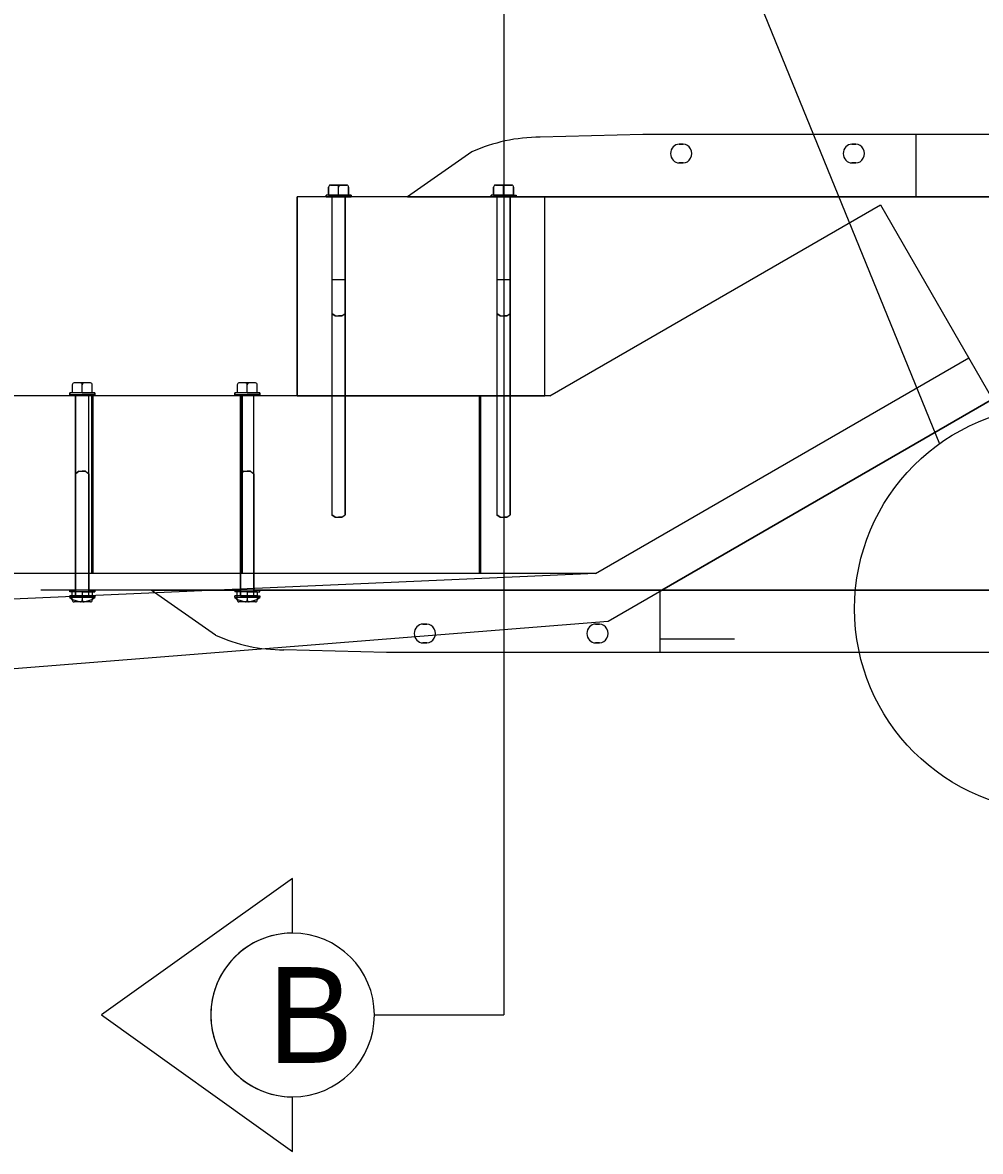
# Model space of a CAD drawing. Extents: x 10028 to 81668, y 3581 to 11018.
# Drawn here: x 17603.6 to 17755.7, y 8654.7 to 8833.9 of the extents above; entities that cross this region are included whole.
import ezdxf

# ---------------------------------------------------------------- set-up
doc = ezdxf.new("R2010")
doc.units = 0
for name, color, linetype in [('conPaving', 7, 'Continuous'), ('dsnCellsNorthArrow', 7, 'Continuous'), ('dsnTextTabulation', 7, 'Continuous'), ('Level 9', 7, 'Continuous')]:
    doc.layers.add(name, color=color, linetype=linetype)

msp = doc.modelspace()

# ---------------------------------------------------------------- linework, layer by layer
at = {"layer": 'conPaving'}
for p, q in [((17702.09, 8816.12), (17685.78, 8815.68)), ((17987.17, 8816.12), (17702.09, 8816.12)), ((17674.94, 8813.36), (17664.69, 8806.21)), ((17707.85, 8814.58), (17708.52, 8814.58)), ((17735.28, 8814.58), (17735.95, 8814.58)), ((17708.52, 8811.61), (17707.85, 8811.61)), ((17735.95, 8811.61), (17735.28, 8811.61)), ((17652.17, 8807.76), (17652.17, 8806.5)), ((17654.04, 8808.08), (17652.45, 8808.08)), ((17655.07, 8808.08), (17654.04, 8808.08)), ((17655.35, 8806.5), (17655.35, 8807.76)), ((17652.17, 8806.5), (17651.77, 8806.5)), ((17651.77, 8806.5), (17651.77, 8806.21)), ((17651.77, 8806.21), (17652.7, 8806.21)), ((17652.7, 8806.21), (17652.7, 8787.72)), ((17654.82, 8787.72), (17654.82, 8806.21)), ((17654.82, 8806.21), (17655.75, 8806.21)), ((17655.75, 8806.5), (17655.35, 8806.5)), ((17655.75, 8806.21), (17655.75, 8806.5)), ((17664.69, 8806.21), (17678.91, 8806.21)), ((17678.91, 8806.21), (17678.91, 8787.72)), ((17681.03, 8787.72), (17681.03, 8806.21)), ((17681.03, 8806.21), (18008.23, 8806.21)), ((17652.7, 8793.03), (17652.7, 8755.74)), ((17654.82, 8793.03), (17652.7, 8793.03)), ((17654.82, 8755.74), (17654.82, 8793.03)), ((17678.91, 8793.03), (17678.91, 8755.74)), ((17681.03, 8793.03), (17678.91, 8793.03)), ((17681.03, 8755.74), (17681.03, 8793.03)), ((17652.7, 8787.72), (17653.23, 8787.34)), ((17653.23, 8787.34), (17653.76, 8787.34)), ((17653.76, 8787.34), (17654.29, 8787.34)), ((17654.29, 8787.34), (17654.82, 8787.72)), ((17678.91, 8787.72), (17679.44, 8787.34)), ((17679.44, 8787.34), (17679.97, 8787.34)), ((17679.97, 8787.34), (17680.5, 8787.34)), ((17680.5, 8787.34), (17681.03, 8787.72)), ((17611.45, 8776.37), (17611.45, 8775.11)), ((17613.32, 8776.68), (17611.73, 8776.68)), ((17614.35, 8776.68), (17613.32, 8776.68)), ((17614.63, 8775.11), (17614.63, 8776.37)), ((17637.66, 8776.37), (17637.66, 8775.11)), ((17639.54, 8776.68), (17637.94, 8776.68)), ((17640.56, 8776.68), (17639.54, 8776.68)), ((17640.85, 8775.11), (17640.85, 8776.37)), ((17611.45, 8775.11), (17611.05, 8775.11)), ((17611.05, 8775.11), (17611.05, 8774.81)), ((17611.05, 8774.81), (17611.98, 8774.81)), ((17611.98, 8774.81), (17611.98, 8742.89)), ((17614.1, 8742.89), (17614.1, 8774.81)), ((17614.1, 8774.81), (17615.03, 8774.81)), ((17615.03, 8775.11), (17614.63, 8775.11)), ((17615.03, 8774.81), (17615.03, 8775.11)), ((17637.66, 8775.11), (17637.26, 8775.11)), ((17637.26, 8775.11), (17637.26, 8774.81)), ((17637.26, 8774.81), (17638.19, 8774.81)), ((17638.19, 8774.81), (17638.19, 8742.89)), ((17640.31, 8742.89), (17640.31, 8774.81)), ((17640.31, 8774.81), (17641.24, 8774.81)), ((17641.24, 8775.11), (17640.85, 8775.11)), ((17641.24, 8774.81), (17641.24, 8775.11)), ((17611.98, 8762.26), (17612.51, 8762.65)), ((17611.98, 8743.77), (17611.98, 8762.26)), ((17612.51, 8762.65), (17613.04, 8762.65)), ((17613.04, 8762.65), (17613.57, 8762.65)), ((17613.57, 8762.65), (17614.1, 8762.26)), ((17614.1, 8762.26), (17614.1, 8743.77)), ((17638.19, 8762.26), (17638.72, 8762.65)), ((17638.19, 8743.77), (17638.19, 8762.26)), ((17638.72, 8762.65), (17639.25, 8762.65)), ((17639.25, 8762.65), (17639.78, 8762.65)), ((17639.78, 8762.65), (17640.31, 8762.26)), ((17640.31, 8762.26), (17640.31, 8743.77)), ((17652.7, 8755.74), (17653.23, 8755.35)), ((17654.29, 8755.35), (17654.82, 8755.74)), ((17678.91, 8755.74), (17679.44, 8755.35)), ((17680.5, 8755.35), (17681.03, 8755.74)), ((17653.23, 8755.35), (17653.76, 8755.35)), ((17653.76, 8755.35), (17654.29, 8755.35)), ((17679.44, 8755.35), (17679.97, 8755.35)), ((17679.97, 8755.35), (17680.5, 8755.35)), ((17611.05, 8743.48), (17611.05, 8743.77)), ((17611.05, 8743.77), (17611.98, 8743.77)), ((17611.45, 8743.48), (17611.05, 8743.48)), ((17611.45, 8742.22), (17611.45, 8743.48)), ((17614.1, 8743.77), (17615.03, 8743.77)), ((17615.03, 8743.48), (17614.63, 8743.48)), ((17614.63, 8743.48), (17614.63, 8742.22)), ((17615.03, 8743.77), (17615.03, 8743.48)), ((17634.22, 8736.63), (17623.97, 8743.77)), ((17623.97, 8743.77), (17638.19, 8743.77)), ((17640.31, 8743.77), (17967.51, 8743.77)), ((17613.32, 8741.91), (17611.73, 8741.91)), ((17611.98, 8742.89), (17614.1, 8742.89)), ((17614.35, 8741.91), (17613.32, 8741.91)), ((17638.19, 8742.89), (17640.31, 8742.89)), ((17667.8, 8738.38), (17667.13, 8738.38)), ((17695.23, 8738.38), (17694.56, 8738.38)), ((17661.37, 8733.87), (17645.06, 8734.3)), ((17667.13, 8735.41), (17667.8, 8735.41)), ((17694.56, 8735.41), (17695.23, 8735.41)), ((17946.45, 8733.87), (17661.37, 8733.87))]:
    msp.add_line(p, q, dxfattribs=at)
msp.add_lwpolyline([(17757.63, 8774.09), (17705.12, 8743.77), (17769.47, 8743.77), (17769.47, 8752.59)], dxfattribs=at)
for centre in [(17613.04, 8745.29), (17639.25, 8745.29)]:
    msp.add_arc(centre, 3.35, 233.5244, 306.4756, dxfattribs=at)
for centre, major_axis, ratio, start_param, end_param in [((17685.78, 8790.15), (-25.97, 0), 0.98332, 4.712389, 5.142831), ((17707.85, 8813.09), (0, -1.49), 0.899999, 3.141593, 6.283185), ((17708.52, 8813.09), (0, -1.49), 0.899999, 0, 3.141593), ((17735.28, 8813.09), (0, -1.49), 0.899999, 3.141593, 6.283185), ((17735.95, 8813.09), (0, -1.49), 0.899999, 0, 3.141593), ((17652.45, 8807.76), (0, -0.315), 0.899999, 3.141593, 4.712389), ((17655.07, 8807.76), (0, -0.315), 0.899999, 1.570796, 3.141593), ((17611.73, 8776.37), (0, -0.315), 0.899999, 3.141593, 4.712389), ((17614.35, 8776.37), (0, -0.315), 0.899999, 1.570796, 3.141593), ((17637.94, 8776.37), (0, -0.315), 0.899999, 3.141593, 4.712389), ((17640.56, 8776.37), (0, -0.315), 0.899999, 1.570796, 3.141593), ((17611.73, 8742.22), (0, -0.315), 0.899999, 4.712389, 6.283185), ((17614.35, 8742.22), (0, -0.315), 0.899999, 6.283185, 7.853982), ((17667.13, 8736.89), (0, -1.49), 0.899999, 3.141593, 6.283185), ((17667.8, 8736.89), (0, -1.49), 0.899999, 0, 3.141593), ((17694.56, 8736.89), (0, -1.49), 0.899999, 3.141593, 6.283185), ((17695.23, 8736.89), (0, -1.49), 0.899999, 0, 3.141593), ((17645.06, 8759.83), (-25.97, 0), 0.98332, 1.140354, 1.570796)]:
    msp.add_ellipse(centre, major_axis=major_axis, ratio=ratio, start_param=start_param, end_param=end_param, dxfattribs=at)
at = {"layer": 'dsnCellsNorthArrow'}
for p, q in [((17646.45, 8697.99), (17616.11, 8676.33)), ((17646.45, 8689.33), (17646.45, 8697.99)), ((17616.11, 8676.33), (17646.45, 8654.66)), ((17646.45, 8654.66), (17646.45, 8663.32))]:
    msp.add_line(p, q, dxfattribs=at)
for start, end in [(89.9948, 270.0052), (90.0052, 269.9948), (270.0052, 89.9948)]:
    msp.add_arc((17646.45, 8676.32), 13, start, end, dxfattribs=at)
at = {"layer": 'dsnTextTabulation'}
for p, q in [((17681.71, 8932.58), (17749.2, 8767.02)), ((17680.01, 8865.47), (17680.01, 8676.32)), ((17687.31, 8774.63), (17739.82, 8804.94)), ((17739.82, 8804.94), (17757.63, 8774.09)), ((17694.57, 8746.43), (17753.85, 8780.65)), ((17687.31, 8774.63), (17511.6, 8774.63)), ((17614.49, 8774.63), (17614.49, 8746.43)), ((17614.71, 8774.63), (17614.71, 8746.43)), ((17638.24, 8774.63), (17638.24, 8746.43)), ((17638.46, 8774.63), (17638.46, 8746.43)), ((17676.09, 8774.63), (17676.09, 8746.43)), ((17676.31, 8774.63), (17676.31, 8746.43)), ((17696.58, 8738.84), (17757.63, 8774.09)), ((17694.57, 8746.43), (17511.6, 8746.43)), ((17511.8, 8724.18), (17696.58, 8738.84)), ((17659.45, 8676.32), (17680.01, 8676.32))]:
    msp.add_line(p, q, dxfattribs=at)
at = {"layer": 'Level 9'}
for p, q in [((17987.17, 8816.12), (17702.09, 8816.12)), ((17745.51, 8806.21), (17745.51, 8816.12)), ((17652.17, 8807.76), (17652.17, 8806.5)), ((17652.17, 8806.5), (17652.17, 8807.76)), ((17652.17, 8806.5), (17652.17, 8807.76)), ((17654.04, 8808.08), (17652.45, 8808.08)), ((17652.45, 8808.08), (17653.47, 8808.08)), ((17652.45, 8808.08), (17653.47, 8808.08)), ((17653.47, 8808.08), (17655.07, 8808.08)), ((17653.47, 8808.08), (17655.07, 8808.08)), ((17653.76, 8806.5), (17653.76, 8807.76)), ((17653.76, 8806.5), (17653.76, 8807.76)), ((17653.76, 8806.5), (17653.76, 8807.76)), ((17655.07, 8808.08), (17654.04, 8808.08)), ((17655.35, 8806.5), (17655.35, 8807.76)), ((17655.35, 8807.76), (17655.35, 8806.5)), ((17655.35, 8807.76), (17655.35, 8806.5)), ((17678.38, 8807.76), (17678.38, 8806.5)), ((17678.38, 8806.5), (17678.38, 8807.76)), ((17678.38, 8806.5), (17678.38, 8807.76)), ((17680.26, 8808.08), (17678.66, 8808.08)), ((17678.66, 8808.08), (17679.69, 8808.08)), ((17678.66, 8808.08), (17679.69, 8808.08)), ((17679.69, 8808.08), (17681.28, 8808.08)), ((17679.69, 8808.08), (17681.28, 8808.08)), ((17679.97, 8806.5), (17679.97, 8807.76)), ((17679.97, 8806.5), (17679.97, 8807.76)), ((17679.97, 8806.5), (17679.97, 8807.76)), ((17681.28, 8808.08), (17680.26, 8808.08)), ((17681.57, 8806.5), (17681.57, 8807.76)), ((17681.57, 8807.76), (17681.57, 8806.5)), ((17681.57, 8807.76), (17681.57, 8806.5)), ((18042.06, 8806.21), (17647.2, 8806.21)), ((17647.2, 8806.21), (17647.2, 8774.63)), ((17686.53, 8806.21), (17647.2, 8806.21)), ((17647.2, 8774.63), (17647.2, 8806.21)), ((17653.76, 8806.5), (17651.77, 8806.5)), ((17651.77, 8806.21), (17651.77, 8806.5)), ((17653.76, 8806.5), (17651.77, 8806.5)), ((17651.77, 8806.5), (17651.77, 8806.21)), ((17653.76, 8806.5), (17651.77, 8806.5)), ((17651.77, 8806.5), (17651.77, 8806.21)), ((17655.75, 8806.21), (17651.77, 8806.21)), ((17651.77, 8806.21), (17655.75, 8806.21)), ((17651.77, 8806.21), (17655.75, 8806.21)), ((17655.35, 8806.5), (17652.17, 8806.5)), ((17652.17, 8806.5), (17655.35, 8806.5)), ((17652.17, 8806.5), (17655.35, 8806.5)), ((17653.76, 8806.21), (17652.7, 8806.21)), ((17652.7, 8806.21), (17652.7, 8787.72)), ((17653.76, 8806.5), (17655.75, 8806.5)), ((17653.76, 8806.5), (17655.75, 8806.5)), ((17653.76, 8806.5), (17655.75, 8806.5)), ((17653.76, 8806.21), (17654.82, 8806.21)), ((17653.76, 8806.21), (17654.82, 8806.21)), ((17654.82, 8806.21), (17654.82, 8787.72)), ((17655.75, 8806.5), (17655.75, 8806.21)), ((17655.75, 8806.21), (17655.75, 8806.5)), ((17655.75, 8806.21), (17655.75, 8806.5)), ((17679.97, 8806.5), (17677.98, 8806.5)), ((17677.98, 8806.21), (17677.98, 8806.5)), ((17679.97, 8806.5), (17677.98, 8806.5)), ((17677.98, 8806.5), (17677.98, 8806.21)), ((17679.97, 8806.5), (17677.98, 8806.5)), ((17677.98, 8806.5), (17677.98, 8806.21)), ((17681.96, 8806.21), (17677.98, 8806.21)), ((17677.98, 8806.21), (17681.96, 8806.21)), ((17677.98, 8806.21), (17681.96, 8806.21)), ((17681.57, 8806.5), (17678.38, 8806.5)), ((17678.38, 8806.5), (17681.57, 8806.5)), ((17678.38, 8806.5), (17681.57, 8806.5)), ((17679.97, 8806.21), (17678.91, 8806.21)), ((17678.91, 8806.21), (17678.91, 8787.72)), ((17679.97, 8806.5), (17681.96, 8806.5)), ((17679.97, 8806.5), (17681.96, 8806.5)), ((17679.97, 8806.5), (17681.96, 8806.5)), ((17679.97, 8806.21), (17681.03, 8806.21)), ((17679.97, 8806.21), (17681.03, 8806.21)), ((17681.03, 8806.21), (17681.03, 8787.72)), ((17681.96, 8806.5), (17681.96, 8806.21)), ((17681.96, 8806.21), (17681.96, 8806.5)), ((17681.96, 8806.21), (17681.96, 8806.5)), ((17686.53, 8774.63), (17686.53, 8806.21)), ((17686.53, 8774.63), (17686.53, 8806.21)), ((17652.7, 8793.03), (17652.7, 8755.74)), ((17654.82, 8793.03), (17654.82, 8755.74)), ((17678.91, 8793.03), (17678.91, 8755.74)), ((17681.03, 8793.03), (17681.03, 8755.74)), ((17653.23, 8787.34), (17652.7, 8787.72)), ((17653.23, 8787.34), (17653.76, 8787.34)), ((17654.29, 8787.34), (17653.76, 8787.34)), ((17654.29, 8787.34), (17654.82, 8787.72)), ((17679.44, 8787.34), (17678.91, 8787.72)), ((17679.44, 8787.34), (17679.97, 8787.34)), ((17680.5, 8787.34), (17679.97, 8787.34)), ((17680.5, 8787.34), (17681.03, 8787.72)), ((17611.45, 8776.37), (17611.45, 8775.11)), ((17613.32, 8776.68), (17611.73, 8776.68)), ((17613.04, 8775.11), (17613.04, 8776.37)), ((17614.35, 8776.68), (17613.32, 8776.68)), ((17614.63, 8775.11), (17614.63, 8776.37)), ((17637.66, 8776.37), (17637.66, 8775.11)), ((17639.54, 8776.68), (17637.94, 8776.68)), ((17639.25, 8775.11), (17639.25, 8776.37)), ((17640.56, 8776.68), (17639.54, 8776.68)), ((17640.85, 8775.11), (17640.85, 8776.37)), ((17613.04, 8775.11), (17611.05, 8775.11)), ((17611.05, 8774.81), (17611.05, 8775.11)), ((17615.03, 8774.81), (17611.05, 8774.81)), ((17614.63, 8775.11), (17611.45, 8775.11)), ((17613.04, 8774.81), (17611.98, 8774.81)), ((17611.98, 8742.89), (17611.98, 8774.81)), ((17613.04, 8775.11), (17615.03, 8775.11)), ((17614.1, 8742.89), (17614.1, 8774.81)), ((17615.03, 8775.11), (17615.03, 8774.81)), ((17639.25, 8775.11), (17637.26, 8775.11)), ((17637.26, 8774.81), (17637.26, 8775.11)), ((17641.24, 8774.81), (17637.26, 8774.81)), ((17640.85, 8775.11), (17637.66, 8775.11)), ((17639.25, 8774.81), (17638.19, 8774.81)), ((17638.19, 8742.89), (17638.19, 8774.81)), ((17639.25, 8775.11), (17641.24, 8775.11)), ((17640.31, 8742.89), (17640.31, 8774.81)), ((17641.24, 8775.11), (17641.24, 8774.81)), ((17647.2, 8774.63), (17686.53, 8774.63)), ((17647.2, 8774.63), (17686.53, 8774.63)), ((17647.2, 8774.63), (17686.53, 8774.63)), ((17612.51, 8762.65), (17611.98, 8762.26)), ((17611.98, 8743.77), (17611.98, 8762.26)), ((17612.51, 8762.65), (17613.04, 8762.65)), ((17613.57, 8762.65), (17613.04, 8762.65)), ((17613.57, 8762.65), (17614.1, 8762.26)), ((17614.1, 8743.77), (17614.1, 8762.26)), ((17638.72, 8762.65), (17638.19, 8762.26)), ((17638.19, 8743.77), (17638.19, 8762.26)), ((17638.72, 8762.65), (17639.25, 8762.65)), ((17639.78, 8762.65), (17639.25, 8762.65)), ((17639.78, 8762.65), (17640.31, 8762.26)), ((17640.31, 8743.77), (17640.31, 8762.26)), ((17653.23, 8755.35), (17652.7, 8755.74)), ((17654.29, 8755.35), (17654.82, 8755.74)), ((17679.44, 8755.35), (17678.91, 8755.74)), ((17680.5, 8755.35), (17681.03, 8755.74)), ((17653.23, 8755.35), (17653.76, 8755.35)), ((17654.29, 8755.35), (17653.76, 8755.35)), ((17679.44, 8755.35), (17679.97, 8755.35)), ((17680.5, 8755.35), (17679.97, 8755.35)), ((17694.57, 8746.43), (17511.6, 8738.31)), ((18001.34, 8743.77), (17606.48, 8743.77)), ((17615.03, 8743.77), (17611.05, 8743.77)), ((17611.05, 8743.77), (17611.05, 8743.48)), ((17613.04, 8743.48), (17611.05, 8743.48)), ((17614.63, 8743.48), (17611.45, 8743.48)), ((17611.45, 8742.22), (17611.45, 8743.48)), ((17613.04, 8743.77), (17611.98, 8743.77)), ((17613.04, 8743.48), (17615.03, 8743.48)), ((17613.04, 8743.48), (17613.04, 8742.22)), ((17614.63, 8743.48), (17614.63, 8742.22)), ((17615.03, 8743.48), (17615.03, 8743.77)), ((17641.24, 8743.77), (17637.26, 8743.77)), ((17637.26, 8743.77), (17637.26, 8743.48)), ((17639.25, 8743.48), (17637.26, 8743.48)), ((17640.85, 8743.48), (17637.66, 8743.48)), ((17637.66, 8742.22), (17637.66, 8743.48)), ((17639.25, 8743.77), (17638.19, 8743.77)), ((17639.25, 8743.48), (17641.24, 8743.48)), ((17639.25, 8743.48), (17639.25, 8742.22)), ((17640.85, 8743.48), (17640.85, 8742.22)), ((17641.24, 8743.48), (17641.24, 8743.77)), ((17704.79, 8743.77), (17704.79, 8733.87)), ((17613.04, 8742.89), (17611.05, 8742.89)), ((17611.05, 8742.6), (17611.05, 8742.89)), ((17615.03, 8742.6), (17611.05, 8742.6)), ((17614.63, 8742.89), (17611.45, 8742.89)), ((17613.32, 8741.91), (17611.73, 8741.91)), ((17613.04, 8742.6), (17611.98, 8742.6)), ((17613.04, 8742.89), (17615.03, 8742.89)), ((17614.35, 8741.91), (17613.32, 8741.91)), ((17615.03, 8742.89), (17615.03, 8742.6)), ((17639.25, 8742.89), (17637.26, 8742.89)), ((17637.26, 8742.6), (17637.26, 8742.89)), ((17641.24, 8742.6), (17637.26, 8742.6)), ((17640.85, 8742.89), (17637.66, 8742.89)), ((17639.54, 8741.91), (17637.94, 8741.91)), ((17639.25, 8742.6), (17638.19, 8742.6)), ((17639.25, 8742.89), (17641.24, 8742.89)), ((17640.56, 8741.91), (17639.54, 8741.91)), ((17641.24, 8742.89), (17641.24, 8742.6)), ((17704.78, 8736.05), (17716.66, 8736.05)), ((17946.45, 8733.87), (17661.37, 8733.87))]:
    msp.add_line(p, q, dxfattribs=at)
for points in [[(17702.09, 8816.12), (17685.78, 8815.68)], [(17674.94, 8813.36), (17664.69, 8806.21)], [(17708.52, 8814.58), (17707.85, 8814.58)], [(17735.95, 8814.58), (17735.28, 8814.58)], [(17707.85, 8811.61), (17708.52, 8811.61)], [(17735.28, 8811.61), (17735.95, 8811.61)], [(17634.22, 8736.63), (17623.97, 8743.77)], [(17667.13, 8738.38), (17667.8, 8738.38)], [(17694.56, 8738.38), (17695.23, 8738.38)], [(17661.37, 8733.87), (17645.06, 8734.3)], [(17667.8, 8735.41), (17667.13, 8735.41)], [(17695.23, 8735.41), (17694.56, 8735.41)]]:
    msp.add_lwpolyline(points, dxfattribs=at)
msp.add_circle((17767.93, 8740.82), 32.2, dxfattribs=at)
for centre, major_axis, ratio, start_param, end_param in [((17685.78, 8790.15), (-25.97, 0), 0.98332, 4.712389, 5.142831), ((17707.85, 8813.09), (0, -1.49), 0.899999, 3.141593, 6.283185), ((17708.52, 8813.09), (0, -1.49), 0.899999, 0, 3.141593), ((17735.28, 8813.09), (0, -1.49), 0.899999, 3.141593, 6.283185), ((17735.95, 8813.09), (0, -1.49), 0.899999, 0, 3.141593), ((17652.45, 8807.76), (0, -0.315), 0.899999, 3.141593, 4.712389), ((17652.45, 8807.76), (0, 0.315), 0.899999, 6.283185, 7.853982), ((17652.45, 8807.76), (0, 0.315), 0.899999, 6.283185, 7.853982), ((17653.47, 8807.76), (0, -0.315), 0.899999, 1.570796, 3.141593), ((17653.47, 8807.76), (0, 0.315), 0.899999, 4.712389, 6.283185), ((17653.47, 8807.76), (0, 0.315), 0.899999, 4.712389, 6.283185), ((17654.04, 8807.76), (0, -0.315), 0.899999, 3.141593, 4.712389), ((17654.04, 8807.76), (0, 0.315), 0.899999, 0, 1.570796), ((17654.04, 8807.76), (0, 0.315), 0.899999, 0, 1.570796), ((17655.07, 8807.76), (0, -0.315), 0.899999, 1.570796, 3.141593), ((17655.07, 8807.76), (0, 0.315), 0.899999, 4.712389, 6.283185), ((17655.07, 8807.76), (0, 0.315), 0.899999, 4.712389, 6.283185), ((17678.66, 8807.76), (0, -0.315), 0.899999, 3.141593, 4.712389), ((17678.66, 8807.76), (0, 0.315), 0.899999, 6.283185, 7.853982), ((17678.66, 8807.76), (0, 0.315), 0.899999, 6.283185, 7.853982), ((17679.69, 8807.76), (0, -0.315), 0.899999, 1.570796, 3.141593), ((17679.69, 8807.76), (0, 0.315), 0.899999, 4.712389, 6.283185), ((17679.69, 8807.76), (0, 0.315), 0.899999, 4.712389, 6.283185), ((17680.26, 8807.76), (0, -0.315), 0.899999, 3.141593, 4.712389), ((17680.26, 8807.76), (0, 0.315), 0.899999, 0, 1.570796), ((17680.26, 8807.76), (0, 0.315), 0.899999, 0, 1.570796), ((17681.28, 8807.76), (0, -0.315), 0.899999, 1.570796, 3.141593), ((17681.28, 8807.76), (0, 0.315), 0.899999, 4.712389, 6.283185), ((17681.28, 8807.76), (0, 0.315), 0.899999, 4.712389, 6.283185), ((17611.73, 8776.37), (0, -0.315), 0.899999, 3.141593, 4.712389), ((17612.76, 8776.37), (0, -0.315), 0.899999, 1.570796, 3.141593), ((17613.32, 8776.37), (0, -0.315), 0.899999, 3.141593, 4.712389), ((17614.35, 8776.37), (0, -0.315), 0.899999, 1.570796, 3.141593), ((17637.94, 8776.37), (0, -0.315), 0.899999, 3.141593, 4.712389), ((17638.97, 8776.37), (0, -0.315), 0.899999, 1.570796, 3.141593), ((17639.54, 8776.37), (0, -0.315), 0.899999, 3.141593, 4.712389), ((17640.56, 8776.37), (0, -0.315), 0.899999, 1.570796, 3.141593), ((17611.73, 8742.22), (0, -0.315), 0.899999, 4.712389, 6.283185), ((17612.76, 8742.22), (0, -0.315), 0.899999, 0, 1.570796), ((17613.32, 8742.22), (0, -0.315), 0.899999, 4.712389, 6.283185), ((17614.35, 8742.22), (0, -0.315), 0.899999, 6.283185, 7.853982), ((17637.94, 8742.22), (0, -0.315), 0.899999, 4.712389, 6.283185), ((17638.97, 8742.22), (0, -0.315), 0.899999, 0, 1.570796), ((17639.54, 8742.22), (0, -0.315), 0.899999, 4.712389, 6.283185), ((17640.56, 8742.22), (0, -0.315), 0.899999, 6.283185, 7.853982), ((17667.13, 8736.89), (0, -1.49), 0.899999, 3.141593, 6.283185), ((17667.8, 8736.89), (0, -1.49), 0.899999, 0, 3.141593), ((17694.56, 8736.89), (0, -1.49), 0.899999, 3.141593, 6.283185), ((17695.23, 8736.89), (0, -1.49), 0.899999, 0, 3.141593), ((17645.06, 8759.83), (-25.97, 0), 0.98332, 1.140354, 1.570796)]:
    msp.add_ellipse(centre, major_axis=major_axis, ratio=ratio, start_param=start_param, end_param=end_param, dxfattribs=at)

# ---------------------------------------------------------------- texts
at = {"layer": 'dsnCellsNorthArrow'}
msp.add_text('B', height=15.2, dxfattribs=at).set_placement((17642.53, 8668.72))

doc.saveas('drawing.dxf')
